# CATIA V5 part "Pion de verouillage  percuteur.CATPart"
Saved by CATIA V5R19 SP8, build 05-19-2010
Part number: Pion de verouillage  percuteur
Bounding box of the stored display mesh (mm): x -2.389 to 2.389, y -2.389 to 2.389, z 0 to 7
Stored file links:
  C:\Users\Arthur\Desktop\Catia parts\GLOCK\Ensemble culasse\Pion de verouillage  percuteur.CATPart
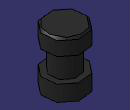
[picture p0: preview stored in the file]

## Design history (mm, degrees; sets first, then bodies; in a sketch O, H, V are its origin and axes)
Set1
  Sketch1 on yz-plane, origin (0, 0, 0), H (0, 1, 0), V (0, 0, 1)
    axis line L1 (0, 0) -> (0, 50)
    line L2 (2.49, 0) -> (1.25, 0)
    line L3 (2.49, 0) -> (2.49, 2)
    line L4 (2.49, 2) -> (1.75, 2)
    line L5 (1.75, 2) -> (1.75, 5)
    line L6 (1.75, 5) -> (2.49, 5)
    line L7 (2.49, 5) -> (2.49, 7)
    line L8 (2.49, 7) -> (0, 7)
    line L9 (1.25, 0) -> (1.25, 5)
    line L10 (1.25, 5) -> (0, 5)
    line L11 (0, 5) -> (0, 7)
    distance L7 L1 = 2.49
    distance L9 L1 = 1.25
    distance L5 L9 = 0.5
    distance L10 L8 = 2
    distance L4 L2 = 2
    distance L6 L4 = 3
    vertical: L1 V, L3 V, L5 V, L7 V, L9 V, L11 V
    horizontal: L2 H, L4 H, L6 H, L8 H, L10 H
    coincidence: L6 L10, L3 L7, L11 L1, L2 H
Body1 (main body)
  Shaft1: profile Sketch1, axis Sketch1.L1, angle 360
  Chamfer1: length 0.25, angle 45, on edge [face of Shaft1 from Sketch1.L7 | face of Shaft1 from Sketch1.L8]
